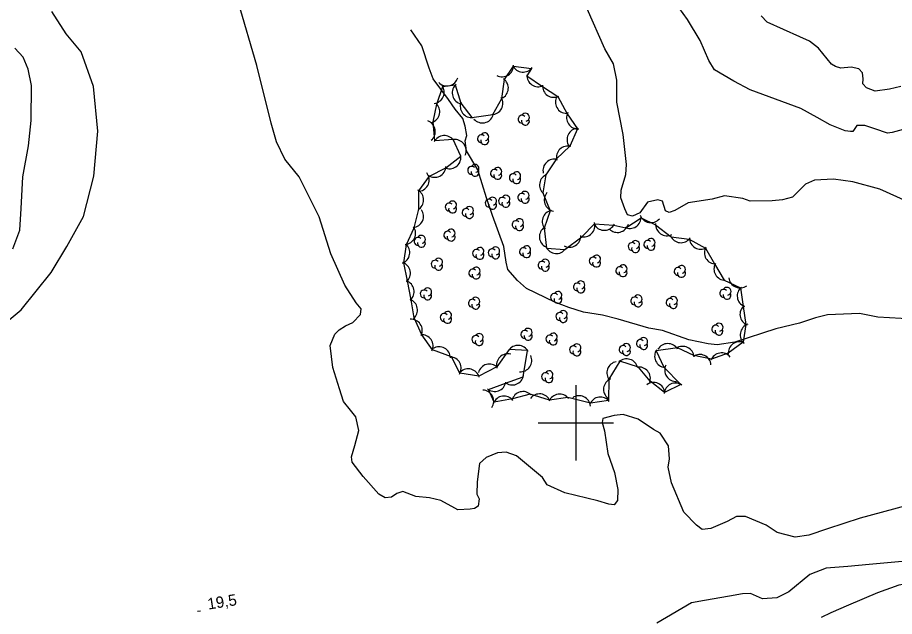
# Model space of a CAD drawing. Extents: x 646142 to 649934, y 5874075 to 5876351.
# Drawn here: x 648451.8 to 648684.5, y 5874948.6 to 5875107.6 of the extents above; entities that cross this region are included whole.
import ezdxf

# ---------------------------------------------------------------- set-up
doc = ezdxf.new("R2010")
doc.units = 0
for name, color, linetype in [('Niveau 1', 7, 'Continuous'), ('Niveau 2', 7, 'Continuous'), ('Niveau 3', 7, 'Continuous'), ('Niveau 4', 7, 'Continuous'), ('Niveau 44', 7, 'Continuous'), ('Niveau 61', 7, 'Continuous')]:
    doc.layers.add(name, color=color, linetype=linetype)

msp = doc.modelspace()

# ---------------------------------------------------------------- linework, layer by layer
at = {"layer": 'Niveau 1'}
for points in [[(648542.85, 5875028.7), (648543.02, 5875030.24), (648541.66, 5875031.83), (648538.65, 5875036.51), (648534.96, 5875044.84), (648531.81, 5875054.63), (648526.57, 5875065.23), (648522.73, 5875069.93), (648520.54, 5875074.58), (648519.13, 5875079.55), (648515.32, 5875094.86), (648510.43, 5875111.45)], [(648584.21, 5874991.2), (648581.52, 5874992.17), (648579.19, 5874992.02), (648576.18, 5874990.74), (648574.38, 5874989.13), (648573.79, 5874984.27), (648573.71, 5874980.99), (648574.32, 5874979.78), (648574.08, 5874977.88), (648573.11, 5874977.18), (648571.95, 5874977.05), (648568.69, 5874976.9), (648567.82, 5874977.27), (648564.18, 5874979.3), (648561.17, 5874980.01), (648557.49, 5874980.4), (648554.05, 5874981.75), (648552.47, 5874981.22), (648551.06, 5874980.24), (648549.33, 5874980.04), (648547.69, 5874981.02), (648543.5, 5874985.68), (648540.58, 5874989.55), (648540.42, 5874990.93), (648541.35, 5874993.96), (648542.4, 5874997.93), (648541.62, 5875001.58), (648540.13, 5875003.28), (648538.32, 5875005.64), (648537.22, 5875009.02), (648535.5, 5875014.66), (648534.8, 5875020.53), (648535.97, 5875023.47), (648537.12, 5875024.66), (648538.88, 5875025.67), (648540.76, 5875026.59), (648542.85, 5875028.7)], [(648666.72, 5874971.78), (648661.77, 5874970.16), (648658.2, 5874969.63), (648653.38, 5874970.82), (648650.45, 5874972.82), (648645.02, 5874975.11), (648642.57, 5874975.06), (648640.16, 5874973.73), (648635.8, 5874971.94), (648633.49, 5874971.67), (648631.96, 5874972.78), (648628.62, 5874976.25), (648625.35, 5874984.04), (648624.5, 5874988.15), (648624.82, 5874990.41), (648624.52, 5874993.87), (648622.37, 5874997.24), (648620.61, 5874998.21), (648616.55, 5875000.89), (648612.53, 5875002.18), (648610.11, 5875001.9), (648607.16, 5875001.09), (648606.93, 5875000.02), (648607.54, 5874997.87), (648608.5, 5874991.79), (648610.27, 5874986.74), (648611.15, 5874982.28), (648611.04, 5874979.35), (648610.12, 5874978.19), (648608.69, 5874978.38), (648605.78, 5874979.21), (648597.09, 5874981.36), (648592.39, 5874983.5), (648591.1, 5874985.46), (648584.21, 5874991.2)], [(648665.18, 5874948.36), (648667.73, 5874949.59), (648672.4, 5874951.65), (648680.09, 5874954.88), (648685.81, 5874956.95), (648693.8, 5874958.57), (648702.89, 5874959.86), (648709.83, 5874960.43), (648720.25, 5874962.34), (648720.98, 5874963.01), (648721.54, 5874965.18), (648721.81, 5874968.83), (648721.25, 5874971.56), (648719.38, 5874975.43), (648715.36, 5874979.75), (648712.33, 5874981.62), (648709.85, 5874981.8), (648706.35, 5874981.74), (648701.69, 5874980.62), (648687.51, 5874977.93), (648675.39, 5874974.65), (648666.72, 5874971.78)]]:
    msp.add_lwpolyline(points, dxfattribs=at)
at = {"layer": 'Niveau 2'}
for points in [[(648686.83, 5875077.83), (648683.9, 5875077.03), (648682.64, 5875076.88), (648679.36, 5875078.02), (648676.7, 5875078.87), (648674.5, 5875078.85), (648673.51, 5875077.34), (648672.82, 5875077.26), (648671.41, 5875077.45), (648667.49, 5875079.09), (648664, 5875081.01), (648659.64, 5875083.41), (648646.25, 5875088.36), (648641.9, 5875090.65), (648636.77, 5875093.66), (648635.31, 5875096.16), (648632.93, 5875101.45), (648629.62, 5875107.01), (648626.13, 5875111.83)], [(648444.16, 5875022.86), (648452.77, 5875029.98), (648460.76, 5875039.87), (648464.92, 5875046.78), (648469.33, 5875054.77), (648472.08, 5875065.44), (648473.07, 5875077.35), (648471.94, 5875089.28), (648468.73, 5875098.41), (648464.75, 5875103.2), (648460.89, 5875109.2)], [(648613.7, 5875055.21), (648612.94, 5875056.75), (648611.89, 5875059.65), (648611.99, 5875061.76), (648613.25, 5875065.85), (648613.4, 5875068.54), (648612.57, 5875076.47), (648610.84, 5875085.11), (648610.84, 5875090.92), (648609.98, 5875095.23), (648607.63, 5875099.27), (648602.99, 5875109.89)], [(648686.22, 5875089.21), (648683.17, 5875088.52), (648679.4, 5875087.97), (648677.09, 5875088.86), (648676.15, 5875089.91), (648676.22, 5875091.31), (648676.02, 5875092.91), (648675.09, 5875093.96), (648673.06, 5875094.42), (648670.31, 5875094.1), (648668.86, 5875094.52), (648667.85, 5875095.21), (648664.33, 5875099.44), (648662.02, 5875101.26), (648659.44, 5875102.47), (648650.73, 5875106.33), (648649.13, 5875108)], [(648692.49, 5875027.33), (648680.15, 5875028.01), (648675.25, 5875028.95), (648666.76, 5875028.67), (648663.59, 5875027.84), (648659.32, 5875026.42), (648653.08, 5875024.88), (648642.17, 5875021.41), (648637.47, 5875020.64), (648635.1, 5875020.94), (648629.95, 5875021.98), (648623, 5875024.44), (648619.3, 5875025.07), (648611.18, 5875027.51), (648607.08, 5875028.55), (648601.96, 5875029.36), (648598.08, 5875030.54), (648594.4, 5875031.98), (648586.84, 5875035.66), (648584.49, 5875037.72), (648581.91, 5875040.68), (648581.45, 5875042.61), (648580.84, 5875046.73), (648577.87, 5875055.01), (648576.26, 5875059.72), (648573.97, 5875067.15), (648570.92, 5875072.15), (648570.61, 5875074.8), (648571.02, 5875076.24), (648570.6, 5875078.75), (648570.01, 5875080.78), (648567.97, 5875083.23), (648566.14, 5875085.81), (648562.1, 5875091.29), (648561.07, 5875094.08), (648559.08, 5875100.02), (648556.19, 5875104.33)], [(648450.56, 5875046.12), (648452.44, 5875051.15), (648452.72, 5875056.85), (648453.22, 5875065.3), (648454.68, 5875073.49), (648455.45, 5875080.19), (648455.51, 5875089.54), (648454.63, 5875093.83), (648453.27, 5875097), (648451.04, 5875099.38)], [(648687.89, 5875058.75), (648680.63, 5875061.98), (648673.52, 5875063.95), (648668.31, 5875064.63), (648663.32, 5875064.4), (648660.89, 5875063.31), (648657.45, 5875059.89), (648654.86, 5875059.13), (648652.09, 5875058.93), (648646.27, 5875058.84), (648644.32, 5875059.55), (648639.45, 5875060.26), (648636.19, 5875059.31), (648629.77, 5875058.34), (648626.28, 5875056.31), (648624.71, 5875055.78), (648623.73, 5875056.25), (648622.95, 5875058.83), (648621.75, 5875059.16), (648619.03, 5875058.5), (648616.91, 5875055.69), (648615.04, 5875054.78), (648613.7, 5875055.21)]]:
    msp.add_lwpolyline(points, dxfattribs=at)
at = {"layer": 'Niveau 3'}
msp.add_line((648499.6, 5874949.96), (648500.39, 5874950.08), dxfattribs=at)
at = {"layer": 'Niveau 4'}
msp.add_lwpolyline([(648726.02, 5874969.78), (648724.25, 5874968.99), (648721.81, 5874968.83), (648719.38, 5874969.59), (648716.28, 5874969.12), (648710.51, 5874968.45), (648696.56, 5874964.85), (648687.51, 5874963.21), (648677.79, 5874962.32), (648672.12, 5874961.78), (648666.44, 5874961.36), (648662.07, 5874959.68), (648656.53, 5874955.07), (648653.32, 5874953.53), (648649.5, 5874953.2), (648646.28, 5874954.69), (648644.18, 5874954.57), (648640.74, 5874953.94), (648634.09, 5874952.81), (648630.65, 5874952.18), (648621.45, 5874946.79)], dxfattribs=at)
at = {"layer": 'Niveau 44'}
for points in [[(648608.65, 5875005.89), (648603.84, 5875005.2), (648597.83, 5875006.66), (648593.02, 5875005.99), (648587.82, 5875007.61), (648583.15, 5875006.31), (648578.26, 5875005.48), (648576.76, 5875008.78), (648581.31, 5875010.47), (648586, 5875012.21), (648587.15, 5875019.16), (648582.31, 5875019.4), (648578.97, 5875014.8), (648574.22, 5875012.36), (648569.22, 5875013.14), (648566.98, 5875017.45), (648561.91, 5875019.35), (648559.14, 5875023.34), (648557.09, 5875027.81), (648556.26, 5875032.59), (648555.28, 5875037.65), (648554.33, 5875042.41), (648555.03, 5875047.33), (648557.07, 5875051.73), (648558.34, 5875056.71), (648558.34, 5875061.56), (648561.11, 5875065.48), (648565.45, 5875067.66), (648569.45, 5875070.71), (648567.37, 5875075.15), (648562.53, 5875074.8), (648562.08, 5875079.84), (648563.06, 5875084.59), (648564.65, 5875089.24), (648567.97, 5875089.65), (648569.41, 5875084.83), (648572.4, 5875081.01), (648577.98, 5875081.82), (648580.32, 5875086.07), (648581.03, 5875091.09), (648583.41, 5875094.61), (648588.22, 5875094.06), (648586.97, 5875092.06)], [(648586.97, 5875092.06), (648591.12, 5875089.27), (648595.15, 5875086.57), (648597.68, 5875082.01), (648600.41, 5875077.99), (648598.34, 5875073.4), (648594.86, 5875070.02), (648592.02, 5875065.8), (648591.18, 5875061.02), (648593.13, 5875056.26), (648591.6, 5875051.65), (648592.21, 5875046.34), (648597.05, 5875045.94), (648601.58, 5875049.34), (648604.96, 5875052.83), (648610.04, 5875052.44), (648613.23, 5875051.75), (648617.3, 5875054.4), (648621.14, 5875052.52), (648625.26, 5875049.3), (648630.08, 5875048.74), (648634.35, 5875046.33), (648636.8, 5875042.14), (648639.32, 5875037.82), (648643.7, 5875035.81), (648644.42, 5875030.86), (648645.12, 5875026.06), (648644.35, 5875021.34), (648640.42, 5875018.49), (648635.96, 5875016.89), (648631.29, 5875017.81), (648626.91, 5875019.9), (648621.27, 5875019.1), (648623.3, 5875014.7), (648627.83, 5875010.16), (648623.46, 5875008.05), (648619.66, 5875011.03), (648616.56, 5875014.77), (648611.66, 5875016.33), (648608.73, 5875011.53), (648608.65, 5875005.89)]]:
    msp.add_lwpolyline(points, dxfattribs=at)
for centre, radius, start, end in [((648580.42, 5875094.82), 3, 242.001, 1.9789), ((648585.98, 5875096.06), 3, 204.3464, 324.3244), ((648589.97, 5875092.17), 3, 176.1552, 296.1332), ((648565.73, 5875092.38), 3, 224.6719, 344.6498), ((648570.15, 5875087.58), 3, 130.3894, 250.3674), ((648579.06, 5875088.83), 3, 294.8724, 54.8504), ((648562.05, 5875087.75), 3, 275.9561, 35.934), ((648594.12, 5875089.38), 3, 176.1552, 296.1332), ((648572.29, 5875084.01), 3, 158.0844, 278.0624), ((648577.61, 5875084.8), 3, 271.1032, 31.0812), ((648597.55, 5875085.1), 3, 156.8944, 276.8724), ((648560.84, 5875082.57), 3, 288.285, 48.2629), ((648575.19, 5875082.58), 3, 221.1299, 341.1079), ((648585.69, 5875080.56), 1.05, 44.1154, 269.804), ((648586.59, 5875080.04), 1.05, 166.9369, 29.6212), ((648586.59, 5875081.09), 1.05, 282.2692, 149.7263), ((648600.51, 5875080.99), 3, 154.0869, 274.0648), ((648559.66, 5875077.27), 3, 310.6241, 70.6021), ((648600.62, 5875075.15), 3, 94.3501, 214.3281), ((648565.08, 5875073.22), 3, 34.1935, 154.1714), ((648574.9, 5875075.38), 1.05, 44.1154, 269.804), ((648575.8, 5875075.91), 1.05, 282.2692, 149.7263), ((648567.85, 5875072.18), 3, 337.0783, 97.0562), ((648575.8, 5875074.86), 1.05, 166.9369, 29.6212), ((648597.83, 5875070.45), 3, 74.2101, 194.188), ((648566.46, 5875070.42), 3, 251.556, 11.5339), ((648594.24, 5875066.96), 3, 74.2101, 194.188), ((648562.49, 5875068.14), 3, 236.6793, 356.6572), ((648572.31, 5875066.99), 1.05, 44.1154, 269.804), ((648573.21, 5875066.47), 1.05, 166.9369, 29.6212), ((648573.21, 5875067.52), 1.05, 282.2692, 149.7263), ((648578.35, 5875066.18), 1.05, 44.1154, 269.804), ((648579.25, 5875066.71), 1.05, 282.2692, 149.7263), ((648584.27, 5875065.55), 1.05, 282.2692, 149.7263), ((648558.04, 5875064.43), 3, 278.3706, 38.3486), ((648579.25, 5875065.66), 1.05, 166.9369, 29.6212), ((648583.37, 5875065.02), 1.05, 44.1154, 269.804), ((648584.27, 5875064.5), 1.05, 166.9369, 29.6212), ((648593.34, 5875063.1), 3, 110.0475, 230.0255), ((648556.58, 5875059.14), 3, 300.0626, 60.0405), ((648577.87, 5875058.79), 1.05, 282.2692, 149.7263), ((648580.51, 5875058.78), 1.05, 44.1154, 269.804), ((648581.41, 5875059.31), 1.05, 282.2692, 149.7263), ((648585.61, 5875059.83), 1.05, 44.1154, 269.804), ((648586.51, 5875059.31), 1.05, 166.9369, 29.6212), ((648586.51, 5875060.36), 1.05, 282.2692, 149.7263), ((648594.58, 5875059.11), 3, 139.2422, 259.2202), ((648566.36, 5875057.26), 1.05, 44.1154, 269.804), ((648567.26, 5875056.74), 1.05, 166.9369, 29.6212), ((648567.26, 5875057.79), 1.05, 282.2692, 149.7263), ((648571.74, 5875056.33), 1.05, 282.2692, 149.7263), ((648576.97, 5875058.26), 1.05, 44.1154, 269.804), ((648577.87, 5875057.74), 1.05, 166.9369, 29.6212), ((648581.41, 5875058.26), 1.05, 166.9369, 29.6212), ((648556.56, 5875054.8), 3, 275.1056, 35.0836), ((648570.84, 5875055.8), 1.05, 44.1154, 269.804), ((648571.74, 5875055.28), 1.05, 166.9369, 29.6212), ((648594.04, 5875053.4), 3, 101.6249, 221.6028), ((648619.87, 5875056.1), 3, 199.1223, 319.1002), ((648584.12, 5875052.58), 1.05, 44.1154, 269.804), ((648585.02, 5875052.06), 1.05, 166.9369, 29.6212), ((648585.02, 5875053.11), 1.05, 282.2692, 149.7263), ((648602, 5875052.31), 3, 255.8912, 15.8691), ((648607.52, 5875054.07), 3, 213.1264, 333.1044), ((648611.02, 5875053.5), 3, 224.0022, 343.9802), ((648614.3, 5875054.55), 3, 243.1376, 3.1155), ((648624.13, 5875052.64), 3, 176.156, 296.1339), ((648554.45, 5875050.27), 3, 275.1056, 35.0836), ((648565.97, 5875049.79), 1.05, 44.1154, 269.804), ((648566.87, 5875050.32), 1.05, 282.2692, 149.7263), ((648593.31, 5875049.35), 3, 123.7906, 243.7685), ((648558.09, 5875048.15), 1.05, 44.1154, 269.804), ((648558.99, 5875047.63), 1.05, 166.9369, 29.6212), ((648558.99, 5875048.68), 1.05, 282.2692, 149.7263), ((648566.87, 5875049.27), 1.05, 166.9369, 29.6212), ((648598.3, 5875049.6), 3, 241.472, 1.4499), ((648614.92, 5875046.75), 1.05, 44.1154, 269.804), ((648615.82, 5875047.28), 1.05, 282.2692, 149.7263), ((648619.03, 5875047.34), 1.05, 44.1154, 269.804), ((648619.93, 5875047.87), 1.05, 282.2692, 149.7263), ((648627.87, 5875050.77), 3, 203.3905, 323.3685), ((648633.1, 5875049.05), 3, 180.1317, 300.1096), ((648552.91, 5875045.14), 3, 290.4177, 50.3956), ((648573.61, 5875044.94), 1.05, 44.1154, 269.804), ((648574.51, 5875045.47), 1.05, 282.2692, 149.7263), ((648577.79, 5875045.08), 1.05, 44.1154, 269.804), ((648578.69, 5875045.61), 1.05, 282.2692, 149.7263), ((648586.03, 5875045.38), 1.05, 44.1154, 269.804), ((648586.93, 5875045.91), 1.05, 282.2692, 149.7263), ((648594.78, 5875047.9), 3, 205.3158, 325.2937), ((648615.82, 5875046.23), 1.05, 166.9369, 29.6212), ((648619.93, 5875046.82), 1.05, 166.9369, 29.6212), ((648637.1, 5875045.13), 3, 150.2736, 270.2515), ((648563.55, 5875042.59), 1.05, 282.2692, 149.7263), ((648574.51, 5875044.42), 1.05, 166.9369, 29.6212), ((648578.69, 5875044.56), 1.05, 166.9369, 29.6212), ((648586.93, 5875044.86), 1.05, 166.9369, 29.6212), ((648591.89, 5875042.32), 1.05, 282.2692, 149.7263), ((648604.57, 5875042.89), 1.05, 44.1154, 269.804), ((648605.47, 5875043.42), 1.05, 282.2692, 149.7263), ((648553.08, 5875039.68), 3, 311.3808, 71.3587), ((648562.65, 5875042.06), 1.05, 44.1154, 269.804), ((648563.55, 5875041.54), 1.05, 166.9369, 29.6212), ((648573.51, 5875040.26), 1.05, 282.2692, 149.7263), ((648590.99, 5875041.79), 1.05, 44.1154, 269.804), ((648591.89, 5875041.27), 1.05, 166.9369, 29.6212), ((648605.47, 5875042.37), 1.05, 166.9369, 29.6212), ((648611.61, 5875040.34), 1.05, 44.1154, 269.804), ((648612.51, 5875040.87), 1.05, 282.2692, 149.7263), ((648627.11, 5875040.15), 1.05, 44.1154, 269.804), ((648628.01, 5875040.68), 1.05, 282.2692, 149.7263), ((648639.62, 5875040.81), 3, 150.2736, 270.2515), ((648572.61, 5875039.73), 1.05, 44.1154, 269.804), ((648573.51, 5875039.21), 1.05, 166.9369, 29.6212), ((648612.51, 5875039.82), 1.05, 166.9369, 29.6212), ((648628.01, 5875039.63), 1.05, 166.9369, 29.6212), ((648554.06, 5875034.78), 3, 311.3808, 71.3587), ((648600.4, 5875036.04), 1.05, 44.1154, 269.804), ((648601.3, 5875036.57), 1.05, 282.2692, 149.7263), ((648643.56, 5875038.78), 3, 186.6451, 306.6231), ((648559.74, 5875034.18), 1.05, 44.1154, 269.804), ((648560.64, 5875033.66), 1.05, 166.9369, 29.6212), ((648560.64, 5875034.71), 1.05, 282.2692, 149.7263), ((648594.32, 5875033.25), 1.05, 44.1154, 269.804), ((648595.22, 5875033.78), 1.05, 282.2692, 149.7263), ((648601.3, 5875035.52), 1.05, 166.9369, 29.6212), ((648616.5, 5875032.86), 1.05, 282.2692, 149.7263), ((648639.2, 5875034.35), 1.05, 44.1154, 269.804), ((648640.1, 5875033.83), 1.05, 166.9369, 29.6212), ((648640.1, 5875034.88), 1.05, 282.2692, 149.7263), ((648645.8, 5875033.66), 3, 128.3043, 248.2822), ((648554.94, 5875029.9), 3, 309.8948, 69.8727), ((648572.51, 5875031.71), 1.05, 44.1154, 269.804), ((648573.41, 5875031.19), 1.05, 166.9369, 29.6212), ((648573.41, 5875032.24), 1.05, 282.2692, 149.7263), ((648595.22, 5875032.73), 1.05, 166.9369, 29.6212), ((648615.6, 5875032.33), 1.05, 44.1154, 269.804), ((648616.5, 5875031.81), 1.05, 166.9369, 29.6212), ((648624.96, 5875031.9), 1.05, 44.1154, 269.804), ((648625.86, 5875031.38), 1.05, 166.9369, 29.6212), ((648625.86, 5875032.43), 1.05, 282.2692, 149.7263), ((648565.93, 5875028.47), 1.05, 282.2692, 149.7263), ((648595.74, 5875028.19), 1.05, 44.1154, 269.804), ((648596.64, 5875028.72), 1.05, 282.2692, 149.7263), ((648646.52, 5875028.72), 3, 128.3043, 248.2822), ((648556.23, 5875024.45), 3, 334.7714, 94.7493), ((648565.03, 5875027.94), 1.05, 44.1154, 269.804), ((648565.93, 5875027.42), 1.05, 166.9369, 29.6212), ((648596.64, 5875027.67), 1.05, 166.9369, 29.6212), ((648587.31, 5875023.99), 1.05, 282.2692, 149.7263), ((648637.08, 5875024.82), 1.05, 44.1154, 269.804), ((648637.98, 5875024.3), 1.05, 166.9369, 29.6212), ((648637.98, 5875025.35), 1.05, 282.2692, 149.7263), ((648646.59, 5875023.3), 3, 109.7881, 229.766), ((648559.08, 5875020.34), 3, 334.7714, 94.7493), ((648573.43, 5875022.08), 1.05, 44.1154, 269.804), ((648574.33, 5875022.61), 1.05, 282.2692, 149.7263), ((648586.41, 5875023.46), 1.05, 44.1154, 269.804), ((648587.31, 5875022.94), 1.05, 166.9369, 29.6212), ((648593.08, 5875022.2), 1.05, 44.1154, 269.804), ((648593.98, 5875021.68), 1.05, 166.9369, 29.6212), ((648593.98, 5875022.73), 1.05, 282.2692, 149.7263), ((648617.98, 5875021.54), 1.05, 282.2692, 149.7263), ((648563.69, 5875017.16), 3, 1.4304, 121.4083), ((648574.33, 5875021.56), 1.05, 166.9369, 29.6212), ((648584.64, 5875017.52), 3, 27.1679, 147.1458), ((648599.35, 5875019.33), 1.05, 44.1154, 269.804), ((648600.25, 5875019.86), 1.05, 282.2692, 149.7263), ((648612.5, 5875019.43), 1.05, 44.1154, 269.804), ((648613.4, 5875019.96), 1.05, 282.2692, 149.7263), ((648617.08, 5875021.01), 1.05, 44.1154, 269.804), ((648617.98, 5875020.49), 1.05, 166.9369, 29.6212), ((648624.37, 5875018), 3, 30.3309, 150.3088), ((648628.34, 5875017.27), 3, 4.4944, 124.4724), ((648643.42, 5875018.49), 3, 65.8546, 185.8326), ((648581.93, 5875015.29), 3, 75.436, 195.414), ((648585.29, 5875016.52), 3, 265.219, 25.1969), ((648600.25, 5875018.81), 1.05, 166.9369, 29.6212), ((648613.4, 5875018.91), 1.05, 166.9369, 29.6212), ((648623.88, 5875017.64), 3, 144.7507, 264.7287), ((648632.85, 5875015.11), 3, 4.4944, 124.4724), ((648638.63, 5875015.53), 3, 39.1438, 159.1218), ((648566.53, 5875014.49), 3, 327.3823, 87.3602), ((648577.03, 5875012.57), 3, 45.3297, 165.3076), ((648611.2, 5875013.23), 3, 100.3108, 220.2887), ((648613.46, 5875013.93), 3, 12.9382, 132.9161), ((648626.55, 5875013.96), 3, 153.3953, 273.3732), ((648571.41, 5875011.31), 3, 14.5186, 134.4966), ((648591.94, 5875012.19), 1.05, 44.1154, 269.804), ((648592.84, 5875012.72), 1.05, 282.2692, 149.7263), ((648616.75, 5875011.77), 3, 339.7213, 99.6992), ((648578.42, 5875011.28), 3, 230.3621, 350.34), ((648583.11, 5875013.01), 3, 230.3621, 350.34), ((648592.84, 5875011.67), 1.05, 166.9369, 29.6212), ((648610.32, 5875008.87), 3, 112.9912, 232.9691), ((648620.61, 5875007.66), 3, 6.4604, 126.4384), ((648575.17, 5875005.65), 3, 327.052, 87.0299), ((648585.96, 5875005.26), 3, 45.4692, 165.4472), ((648626.41, 5875007.52), 3, 55.7705, 175.7485), ((648580.91, 5875004.07), 3, 37.9353, 157.9133), ((648590.32, 5875004.64), 3, 22.616, 142.594), ((648595.67, 5875004.58), 3, 37.9623, 157.9402), ((648600.83, 5875004.16), 3, 4.3807, 124.3586), ((648606.49, 5875003.8), 3, 38.112, 158.0899)]:
    msp.add_arc(centre, radius, start, end, dxfattribs=at)
at = {"layer": 'Niveau 61'}
for points in [[(648600, 5875010), (648600, 5875000), (648600, 5874990)], [(648590, 5875000), (648600, 5875000), (648610, 5875000)]]:
    msp.add_lwpolyline(points, dxfattribs=at)

# ---------------------------------------------------------------- texts
at = {"layer": 'Niveau 3'}
msp.add_text('19,5 ', height=3, rotation=8.9405, dxfattribs=at).set_placement((648502.45, 5874950.37))

doc.saveas('drawing.dxf')
